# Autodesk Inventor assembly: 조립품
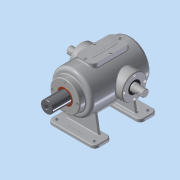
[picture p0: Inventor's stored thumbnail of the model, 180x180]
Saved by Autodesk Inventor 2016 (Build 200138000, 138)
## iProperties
Created: 2018-11
Part Number: 조립품
Material: 일반
Document SubType Name: Assembly
Designer: 공506_43
Author: 공506_43
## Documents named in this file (15)
- C:\Users\공506_43\Desktop\381121V1009\조립품.iam
- C:\Users\공506_43\Desktop\381121V1009\가변스프링.ipt
- C:\Users\공506_43\Desktop\381121V1009\베어링 6205.ipt
- 베어링 6205.ipt
- C:\Users\공506_43\Desktop\381121V1009\본체.ipt
- C:\Users\공506_43\Desktop\381121V1009\볼트 M4x0.7.ipt
- C:\Users\공506_43\Desktop\381121V1009\부시.ipt
- C:\Users\공506_43\Desktop\381121V1009\상부커버.ipt
- C:\Users\공506_43\Desktop\381121V1009\슬라이드 커버.ipt
- C:\Users\공506_43\Desktop\381121V1009\슬라이드.ipt
- C:\Users\공506_43\Desktop\381121V1009\오일실.ipt
- 오일실.ipt
- C:\Users\공506_43\Desktop\381121V1009\육각머리볼트 M4.ipt
- C:\Users\공506_43\Desktop\381121V1009\축 커버.ipt
- C:\Users\공506_43\Desktop\381121V1009\편심축.ipt
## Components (13 placed, 2 different names)
1. 가변스프링:1
2. M4x0.7:3
3. M4x0.7:4
4. M4x0.7:5
5. M4x0.7:6
6. M4x0.7:1
7. M4x0.7:7
8. M4x0.7:8
9. M4x0.7:9
10. M4x0.7:2
11. M4x0.7:10
12. M4x0.7:11
13. M4x0.7:12
